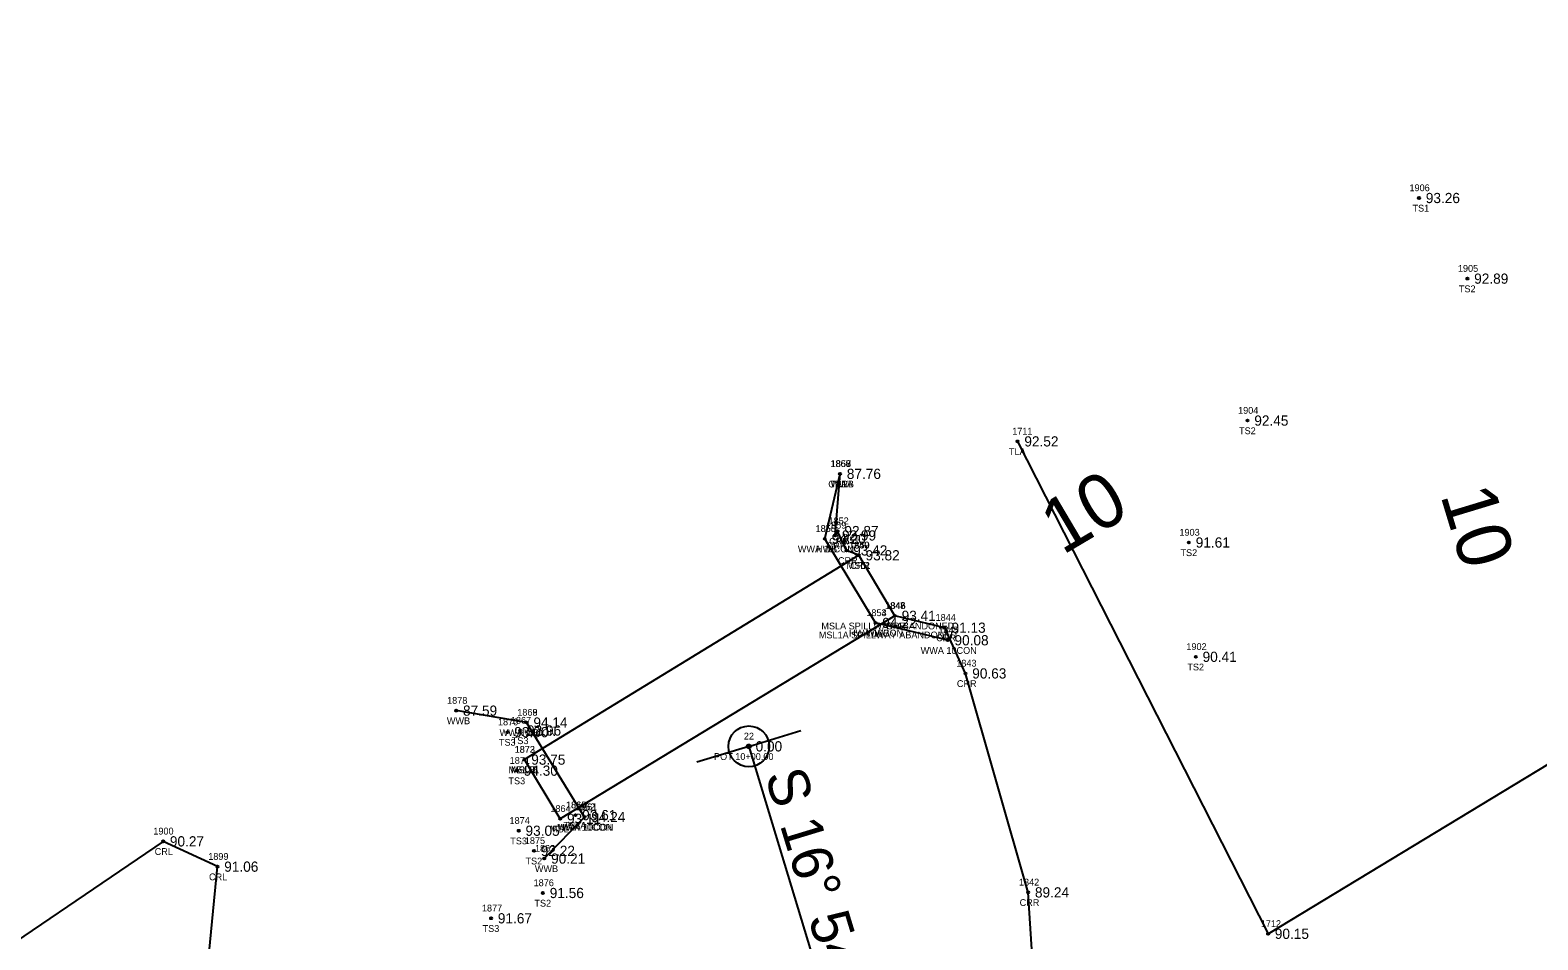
# Model space of a CAD drawing. Extents: x 2529517 to 2532038, y 935000 to 936944.
# Drawn here: x 2531034.4 to 2531256.1, y 936067 to 936200.7 of the extents above; entities that cross this region are included whole.
import ezdxf

# ---------------------------------------------------------------- set-up
doc = ezdxf.new("R2010")
doc.units = 0
for name, color, linetype in [('Default', 7, 'Continuous'), ('RD_DTM_BkLn_txCode', 7, 'Continuous'), ('RD_EX_Bridge', 7, 'Continuous'), ('RD_EX_Bridge_txCode', 7, 'Continuous'), ('RD_EX_H2O', 7, 'Continuous'), ('RD_EX_H2O_txCode', 7, 'Continuous'), ('RD_EX_Misc', 7, 'Continuous'), ('RD_EX_Misc_txCode', 7, 'Continuous'), ('RD_EX_TX_Bridge_ELEV', 7, 'Continuous'), ('RD_EX_TX_H2O_ELEV', 7, 'Continuous'), ('RD_EX_TX_Misc_ELEV', 7, 'Continuous'), ('RD_EX_TX_VEG_ELEV', 7, 'Continuous'), ('RD_EX_VEG', 7, 'Continuous'), ('RD_EX_VEG_txCode', 7, 'Continuous'), ('RD_HC_Cl', 7, 'Continuous'), ('RD_HC_Data', 7, 'Continuous'), ('RD_HC_Data_Tic', 7, 'Continuous'), ('RD_HC_Survey_ELEV', 7, 'Continuous'), ('RD_HC_TX_Sta50', 7, 'Continuous'), ('RD_HC_txCode', 7, 'Continuous'), ('RD_SMD_Locator', 7, 'Continuous')]:
    doc.layers.add(name, color=color, linetype=linetype)

msp = doc.modelspace()

# ---------------------------------------------------------------- linework, layer by layer
at = {"layer": 'Default'}
msp.add_line((2531140.11, 936095.44), (2531159.4, 936031.99), dxfattribs=at)
at = {"layer": 'RD_EX_Bridge'}
for p, q in [((2531151.29, 936125.95), (2531153.52, 936135.49)), ((2531158.73, 936113.58), (2531151.29, 936125.95)), ((2531169.35, 936111.03), (2531158.73, 936113.58)), ((2531107.44, 936098.94), (2531097.09, 936100.69)), ((2531115.94, 936085.05), (2531107.44, 936098.94)), ((2531115.94, 936085.05), (2531110.04, 936078.95))]:
    msp.add_line(p, q, dxfattribs=at)
at = {"layer": 'RD_EX_H2O'}
for points in [[(2531078.88, 935952.28), (2531078.88, 935952.28), (2531082.9, 935955.37), (2531071.89, 935962.43), (2531052.52, 935981.82), (2531042.66, 936018.54), (2531050.4, 936038.59), (2531079.35, 936050.48), (2531076.46, 936052.29), (2531062.77, 936059.41), (2531060.27, 936060.12), (2531061.98, 936077.76), (2531053.99, 936081.48), (2531023.23, 936060.57), (2531009.04, 936063.64), (2530981.92, 936072.85), (2530952.28, 936069.69), (2530922.53, 936086.42), (2530896.36, 936118.01), (2530886.54, 936120.09), (2530870.44, 936126.5), (2530844.88, 936119.11), (2530827.4, 936131.93), (2530794.88, 936161.74)], [(2531169.61, 936003.09), (2531185.12, 936014.09), (2531186.37, 936023.16), (2531184.04, 936029.91), (2531181.18, 936073.98), (2531171.96, 936106.16), (2531168.92, 936112.88), (2531161.58, 936114.63), (2531156.28, 936123.52), (2531154.46, 936124.24), (2531153.17, 936127.08), (2531152.81, 936126.44), (2531153.52, 936135.49)]]:
    msp.add_lwpolyline(points, dxfattribs=at)
at = {"layer": 'RD_EX_Misc'}
for points in [[(2531161.58, 936114.63), (2531156.28, 936123.52), (2531107.12, 936093.49)], [(2531161.58, 936114.63), (2531112.38, 936084.79), (2531107.12, 936093.49)]]:
    msp.add_lwpolyline(points, dxfattribs=at)
at = {"layer": 'RD_EX_VEG'}
msp.add_lwpolyline([(2531179.62, 936140.26), (2531216.45, 936067.89), (2531694.54, 936357.52), (2531717.1, 936375.33), (2531741.26, 936412.31), (2531677.61, 936469.53)], dxfattribs=at)
at = {"layer": 'RD_HC_Cl'}
msp.add_line((2531140.11, 936095.44), (2531159.4, 936031.99), dxfattribs=at)
at = {"layer": 'RD_HC_Data'}
for radius in [3, 0.282]:
    msp.add_circle((2531140.11, 936095.44), radius, dxfattribs=at)
at = {"layer": 'RD_HC_Data_Tic'}
for q in [(2531147.76, 936097.76), (2531132.46, 936093.11)]:
    msp.add_line((2531140.11, 936095.44), q, dxfattribs=at)
at = {"layer": 'RD_SMD_Locator'}
for centre in [(2531238.65, 936176.03), (2531245.76, 936164.18), (2531213.43, 936143.32), (2531179.62, 936140.26), (2531153.52, 936135.49), (2531153.52, 936135.49), (2531153.52, 936135.49), (2531151.29, 936125.95), (2531151.29, 936125.95), (2531152.81, 936126.44), (2531153.17, 936127.08), (2531154.46, 936124.24), (2531156.28, 936123.52), (2531156.28, 936123.52), (2531204.82, 936125.4), (2531161.58, 936114.63), (2531161.58, 936114.63), (2531161.58, 936114.63), (2531158.73, 936113.58), (2531158.73, 936113.58), (2531168.92, 936112.88), (2531169.35, 936111.03), (2531205.83, 936108.6), (2531171.96, 936106.16), (2531097.09, 936100.69), (2531107.44, 936098.94), (2531107.44, 936098.94), (2531104.62, 936097.53), (2531106.5, 936097.77), (2531140.11, 936095.44), (2531107.12, 936093.49), (2531107.12, 936093.49), (2531106.02, 936091.87), (2531112.38, 936084.79), (2531114.62, 936085.33), (2531114.62, 936085.33), (2531115.94, 936085.05), (2531115.94, 936085.05), (2531053.99, 936081.48), (2531106.28, 936083.04), (2531108.53, 936080.08), (2531110.04, 936078.95), (2531061.98, 936077.76), (2531109.84, 936073.89), (2531181.18, 936073.98), (2531102.21, 936070.17), (2531216.45, 936067.89)]:
    msp.add_circle(centre, 0.15, dxfattribs=at)

# ---------------------------------------------------------------- texts
at = {"layer": 'RD_DTM_BkLn_txCode'}
for s, p in [('1906', (2531237.25, 936177.03)), ('TS1', (2531237.69, 936174.03)), ('1905', (2531244.37, 936165.18)), ('TS2', (2531244.51, 936162.18)), ('1904', (2531212.05, 936144.32)), ('TS2', (2531212.19, 936141.32)), ('1858', (2531152.17, 936136.49)), ('TS1A', (2531152.07, 936133.49)), ('1903', (2531203.43, 936126.4)), ('TS2', (2531203.58, 936123.4)), ('1902', (2531204.45, 936109.6)), ('TS2', (2531204.59, 936106.6)), ('1870', (2531103.23, 936098.53)), ('1867', (2531105.13, 936098.77)), ('TS3', (2531105.26, 936095.77)), ('TS3', (2531103.37, 936095.53)), ('1871', (2531104.95, 936092.87)), ('TS3', (2531104.77, 936089.87)), ('1866', (2531113.22, 936086.33)), ('1865', (2531113.25, 936086.33)), ('1874', (2531104.93, 936084.04)), ('TS2A', (2531112.88, 936083.33)), ('TS3A', (2531112.88, 936083.33)), ('TS3', (2531105.04, 936081.04)), ('1875', (2531107.18, 936081.08)), ('TS2', (2531107.28, 936078.08)), ('1876', (2531108.47, 936074.89)), ('TS2', (2531108.59, 936071.89)), ('1877', (2531100.87, 936071.17)), ('TS3', (2531100.97, 936068.17))]:
    msp.add_text(s, height=1, dxfattribs=at).set_placement(p)
at = {"layer": 'RD_EX_Bridge_txCode'}
for s, p in [('1857', (2531152.17, 936136.49)), ('WWB', (2531152.14, 936133.49)), ('1856', (2531149.92, 936126.95)), ('1855', (2531149.94, 936126.95)), ('WWA 10CON', (2531147.32, 936123.95)), ('HWB', (2531149.99, 936123.95)), ('1853', (2531157.39, 936114.58)), ('1854', (2531157.39, 936114.58)), ('HWA 10CON', (2531154.85, 936111.58)), ('WWB', (2531157.35, 936111.58)), ('1845', (2531168, 936112.03)), ('WWA 10CON', (2531165.38, 936109.03)), ('1878', (2531095.75, 936101.69)), ('WWB', (2531095.72, 936098.69)), ('1868', (2531106.07, 936099.94)), ('1869', (2531106.07, 936099.94)), ('WWA 10CON', (2531103.47, 936096.94)), ('HWB', (2531106.15, 936096.94)), ('1862', (2531114.57, 936086.05)), ('1861', (2531114.85, 936086.05)), ('WWA 10CON', (2531111.97, 936083.05)), ('HWA 10CON', (2531112.06, 936083.05)), ('1863', (2531108.67, 936079.95)), ('WWB', (2531108.66, 936076.95))]:
    msp.add_text(s, height=1, dxfattribs=at).set_placement(p)
at = {"layer": 'RD_EX_H2O_txCode'}
for s, p in [('1860', (2531152.11, 936136.49)), ('CRRB', (2531151.79, 936133.49)), ('1859', (2531151.47, 936127.44)), ('1852', (2531151.83, 936128.08)), ('CRR', (2531151.92, 936125.08)), ('1851', (2531153.4, 936125.24)), ('CRR', (2531151.56, 936124.44)), ('1850', (2531154.9, 936124.52)), ('CRR', (2531153.21, 936122.24)), ('CRR', (2531155.03, 936121.52)), ('1846', (2531160.2, 936115.63)), ('1844', (2531167.57, 936113.88)), ('CRR', (2531160.32, 936112.63)), ('CRR', (2531167.66, 936110.88)), ('1843', (2531170.61, 936107.16)), ('CRR', (2531170.7, 936104.16)), ('1900', (2531052.56, 936082.48)), ('CRL', (2531052.76, 936079.48)), ('1899', (2531060.63, 936078.76)), ('CRL', (2531060.75, 936075.76)), ('1842', (2531179.83, 936074.98)), ('CRR', (2531179.93, 936071.98))]:
    msp.add_text(s, height=1, dxfattribs=at).set_placement(p)
at = {"layer": 'RD_EX_Misc_txCode'}
for s, p in [('1849', (2531154.84, 936124.52)), ('MSL1', (2531154.49, 936121.52)), ('1847', (2531160.13, 936115.63)), ('1848', (2531160.14, 936115.63)), ('MSL1A SPILLWAY ABANDONED', (2531150.41, 936111.31)), ('MSLA SPILLWAY ABANDONED', (2531150.78, 936112.63)), ('1872', (2531105.67, 936094.49)), ('1873', (2531105.7, 936094.49)), ('MSL1B', (2531104.78, 936091.49)), ('MSLB', (2531105.15, 936091.49)), ('1864', (2531110.93, 936085.79)), ('MSL', (2531110.88, 936082.79))]:
    msp.add_text(s, height=1, dxfattribs=at).set_placement(p)
at = {"layer": 'RD_EX_TX_Bridge_ELEV'}
for s, p in [('87.76', (2531154.52, 936134.74)), ('94.20', (2531152.29, 936125.2)), ('94.20', (2531152.29, 936125.2)), ('94.22', (2531159.73, 936112.83)), ('94.22', (2531159.73, 936112.83)), ('90.08', (2531170.35, 936110.28)), ('87.59', (2531098.09, 936099.94)), ('94.14', (2531108.44, 936098.19)), ('94.14', (2531108.44, 936098.19)), ('94.24', (2531116.94, 936084.3)), ('94.24', (2531116.94, 936084.3)), ('90.21', (2531111.04, 936078.2))]:
    msp.add_text(s, height=1.5, dxfattribs=at).set_placement(p)
at = {"layer": 'RD_EX_TX_H2O_ELEV'}
for s, p in [('87.76', (2531154.52, 936134.74)), ('92.87', (2531154.17, 936126.33)), ('92.99', (2531153.81, 936125.69)), ('93.42', (2531155.46, 936123.49)), ('93.82', (2531157.28, 936122.77)), ('93.41', (2531162.58, 936113.88)), ('91.13', (2531169.92, 936112.13)), ('90.63', (2531172.96, 936105.41)), ('90.27', (2531054.99, 936080.73)), ('91.06', (2531062.98, 936077.01)), ('89.24', (2531182.18, 936073.23))]:
    msp.add_text(s, height=1.5, dxfattribs=at).set_placement(p)
at = {"layer": 'RD_EX_TX_Misc_ELEV'}
for s, p in [('93.26', (2531239.65, 936175.28)), ('92.89', (2531246.76, 936163.43)), ('92.45', (2531214.43, 936142.57)), ('87.76', (2531154.52, 936134.74)), ('91.61', (2531205.82, 936124.65)), ('93.82', (2531157.28, 936122.77)), ('93.41', (2531162.58, 936113.88)), ('93.41', (2531162.58, 936113.88)), ('90.41', (2531206.83, 936107.85)), ('93.00', (2531105.62, 936096.78)), ('92.96', (2531107.5, 936097.02)), ('94.30', (2531107.02, 936091.12)), ('93.75', (2531108.12, 936092.74)), ('93.75', (2531108.12, 936092.74)), ('93.61', (2531115.62, 936084.58)), ('93.61', (2531115.62, 936084.58)), ('93.05', (2531107.28, 936082.29)), ('93.11', (2531113.38, 936084.04)), ('92.22', (2531109.53, 936079.33)), ('91.56', (2531110.84, 936073.14)), ('91.67', (2531103.21, 936069.42))]:
    msp.add_text(s, height=1.5, dxfattribs=at).set_placement(p)
at = {"layer": 'RD_EX_TX_VEG_ELEV'}
for s, p in [('92.52', (2531180.62, 936139.51)), ('90.15', (2531217.45, 936067.14))]:
    msp.add_text(s, height=1.5, dxfattribs=at).set_placement(p)
at = {"layer": 'RD_EX_VEG_txCode'}
for s, p in [('1711', (2531178.84, 936141.26)), ('TLA', (2531178.36, 936138.26)), ('1712', (2531215.39, 936068.89))]:
    msp.add_text(s, height=1, dxfattribs=at).set_placement(p)
at = {"layer": 'RD_HC_Data'}
msp.add_text('S 16%%d 54\' 35" E', height=6, rotation=286.9097, dxfattribs=at).set_placement((2531142.44, 936091.19))
at = {"layer": 'RD_HC_Survey_ELEV'}
msp.add_text('0.00', height=1.5, dxfattribs=at).set_placement((2531141.11, 936094.69))
at = {"layer": 'RD_HC_TX_Sta50'}
for rotation, p in [(30.6357, (2531186.22, 936123.48)), (286.9097, (2531241.75, 936132.39))]:
    msp.add_text('10', height=8, rotation=rotation, dxfattribs=at).set_placement(p)
at = {"layer": 'RD_HC_txCode'}
for s, p in [('22', (2531139.38, 936096.44)), ('POT 10+00.00', (2531135, 936093.44))]:
    msp.add_text(s, height=1, dxfattribs=at).set_placement(p)

doc.saveas('drawing.dxf')
